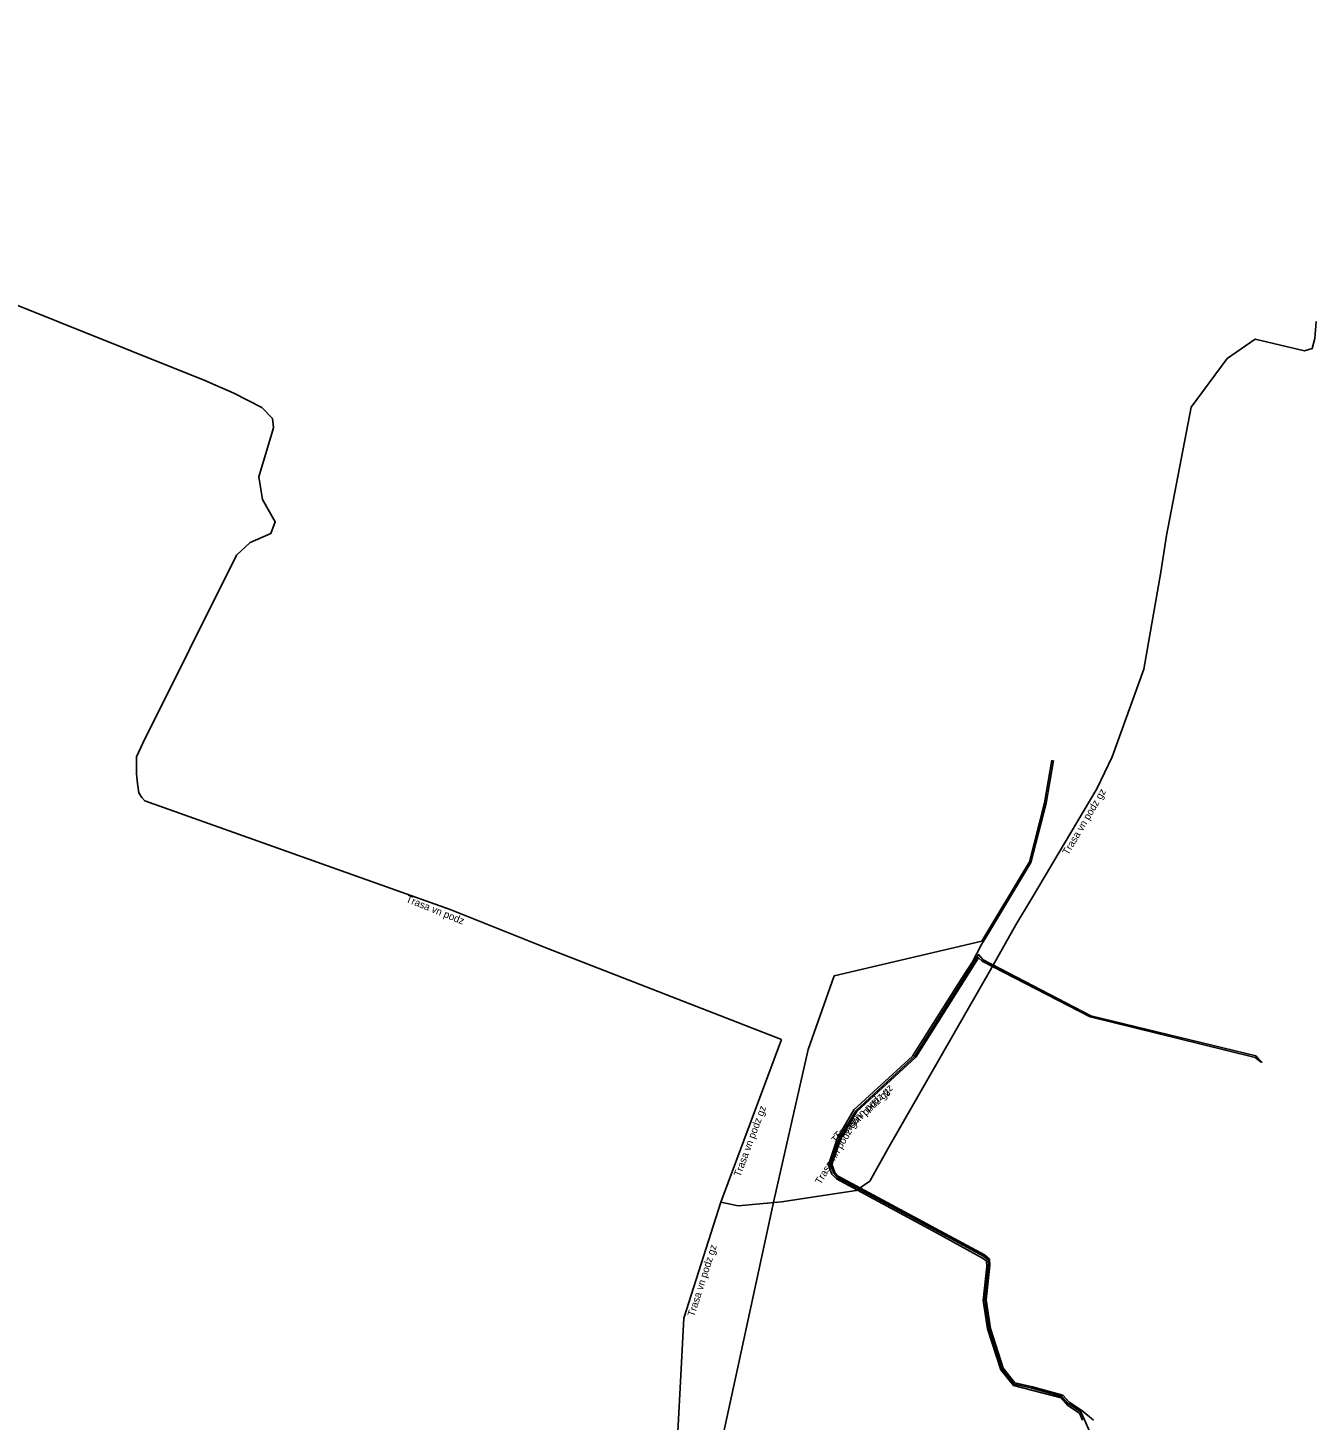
# Model space of a CAD drawing. Extents: x -875087 to -874407, y -1056142 to -1055396.
# Drawn here: x -874544 to -874455.7, y -1055813.9 to -1055718.5 of the extents above; entities that cross this region are included whole.
import ezdxf

# ---------------------------------------------------------------- set-up
doc = ezdxf.new("R2010")
doc.units = 0
for name, color, linetype in [('Popiskový text - Ostatní atributy Trasy', 7, 'Continuous'), ('Spojnice NN', 7, 'Continuous'), ('Spojnice VN', 7, 'Continuous')]:
    doc.layers.add(name, color=color, linetype=linetype)

msp = doc.modelspace()

# ---------------------------------------------------------------- linework, layer by layer
at = {"layer": 'Spojnice NN'}
for points in [[(-874476.442, -1055879.876), (-874476.123, -1055880.406), (-874477.372, -1055886.555), (-874489.374, -1055884.233), (-874490.02, -1055884.117), (-874489.806, -1055882.948), (-874487.818, -1055874.674), (-874485.599, -1055861.083), (-874491.806, -1055849.075), (-874499.666, -1055830.214), (-874495.282, -1055810.035), (-874492.855, -1055798.848), (-874490.498, -1055788.478), (-874488.735, -1055783.434), (-874478.596, -1055781.048), (-874475.337, -1055775.613), (-874474.306, -1055771.567), (-874473.798, -1055768.649)], [(-874473.699, -1055768.666), (-874474.208, -1055771.589), (-874475.244, -1055775.651), (-874478.188, -1055780.57), (-874478.51, -1055781.099), (-874478.618, -1055781.278), (-874479.256, -1055782.458), (-874479.965, -1055783.578), (-874483.348, -1055788.919), (-874487.374, -1055792.616), (-874488.488, -1055794.516), (-874489.116, -1055796.372), (-874488.874, -1055797.014), (-874488.56, -1055797.342), (-874481.664, -1055801.069), (-874478.508, -1055802.796), (-874478.296, -1055802.969), (-874478.267, -1055803.335), (-874478.507, -1055805.664), (-874478.228, -1055807.609), (-874477.304, -1055810.428), (-874476.428, -1055811.497), (-874473.166, -1055812.344), (-874472.713, -1055812.864), (-874471.924, -1055813.383), (-874471.717, -1055813.872)], [(-874459.423, -1055789.295), (-874459.435, -1055789.356), (-874459.828, -1055788.912), (-874471.126, -1055786.16), (-874478.52, -1055782.337), (-874478.838, -1055781.953), (-874479.165, -1055782.516), (-874483.198, -1055788.926), (-874487.248, -1055792.666), (-874488.331, -1055794.487), (-874488.997, -1055796.321), (-874488.757, -1055796.942), (-874488.507, -1055797.243), (-874483.647, -1055799.851), (-874482.116, -1055800.669), (-874478.487, -1055802.633), (-874478.177, -1055802.899), (-874478.15, -1055803.258), (-874478.401, -1055805.632), (-874478.118, -1055807.602), (-874477.23, -1055810.358), (-874476.396, -1055811.4), (-874475.187, -1055811.68), (-874473.127, -1055812.248), (-874472.684, -1055812.719), (-874471.816, -1055813.293), (-874471.57, -1055813.849)], [(-874470.96, -1055813.87), (-874471.76, -1055813.21), (-874472.63, -1055812.63), (-874473.06, -1055812.17), (-874475.14, -1055811.59), (-874476.34, -1055811.31), (-874477.14, -1055810.31), (-874478.02, -1055807.58), (-874478.3, -1055805.63), (-874478.05, -1055803.26), (-874478.08, -1055802.85), (-874478.43, -1055802.55), (-874488.44, -1055797.16), (-874488.67, -1055796.89), (-874488.89, -1055796.32), (-874488.24, -1055794.53), (-874487.17, -1055792.73), (-874483.12, -1055788.99), (-874478.825, -1055782.191), (-874478.586, -1055782.43), (-874471.178, -1055786.226), (-874461.916, -1055788.523), (-874459.867, -1055789.031), (-874459.474, -1055789.336), (-874459.423, -1055789.295)], [(-874471.57, -1055813.849), (-874469.534, -1055818.469), (-874464.404, -1055828.728), (-874462.171, -1055835.73), (-874458.665, -1055845.492), (-874457.632, -1055847.133), (-874456.235, -1055848.653), (-874458.422, -1055863.908), (-874458.653, -1055864.115), (-874463.528, -1055864.698), (-874468.98, -1055864.215), (-874475.059, -1055862.826), (-874480.473, -1055866.45), (-874486.441, -1055870.715), (-874487.718, -1055877.523), (-874488.933, -1055883.904), (-874477.628, -1055886.093), (-874477.456, -1055885.202), (-874476.534, -1055880.44), (-874476.442, -1055879.876)]]:
    msp.add_lwpolyline(points, dxfattribs=at)
at = {"layer": 'Spojnice VN'}
for points in [[(-874592.144, -1055718.468), (-874531.837, -1055742.641), (-874529.864, -1055743.504), (-874527.952, -1055744.491), (-874527.212, -1055745.231), (-874527.15, -1055745.848), (-874527.212, -1055746.094), (-874528.137, -1055749.239), (-874527.89, -1055750.781), (-874527.027, -1055752.322), (-874527.336, -1055753.124), (-874528.753, -1055753.741), (-874529.679, -1055754.604), (-874536.092, -1055767.492), (-874536.524, -1055768.417), (-874536.524, -1055769.589)], [(-874496.48, -1055798.93), (-874495.3, -1055799.18), (-874492.33, -1055798.9), (-874487.22, -1055798.14), (-874486.29, -1055797.5), (-874485.04, -1055795.28), (-874477.83, -1055782.69), (-874476.27, -1055779.93), (-874475.21, -1055778.16), (-874470.73, -1055770.62), (-874469.68, -1055768.41), (-874467.51, -1055762.42), (-874466.35, -1055755.76), (-874465.96, -1055753.25), (-874464.26, -1055744.46), (-874461.8, -1055741.13), (-874459.87, -1055739.8), (-874456.49, -1055740.6), (-874455.96, -1055740.45), (-874455.78, -1055739.75), (-874455.697, -1055738.589)], [(-874536.524, -1055769.589), (-874536.466, -1055770.237), (-874536.378, -1055770.887), (-874536.156, -1055771.213), (-874535.963, -1055771.434), (-874515.04, -1055778.878), (-874508.3, -1055781.575), (-874492.34, -1055787.79)], [(-874496.48, -1055798.93), (-874492.34, -1055787.79)], [(-874499.02, -1055806.89), (-874496.48, -1055798.93)], [(-874499.02, -1055806.89), (-874500.268, -1055830.266), (-874492.837, -1055847.885), (-874483.497, -1055865.879), (-874473.648, -1055877.348), (-874476.357, -1055879.881)]]:
    msp.add_lwpolyline(points, dxfattribs=at)

# ---------------------------------------------------------------- texts
at = {"layer": 'Popiskový text - Ostatní atributy Trasy'}
for s, rotation, p in [('Trasa vn podz gz', 59.28272, (-874472.691, -1055775.193)), ('Trasa vn podz', 338.19383, (-874518.118, -1055778.347)), ('Trasa nn podz gz', 42.72114, (-874488.627, -1055794.96)), ('Trasa nn podz gz', 42.72143, (-874488.46, -1055794.67)), ('Trasa vn podz gz', 69.61323, (-874495.157, -1055797.236)), ('Trasa nn podz gz', 59.60868, (-874489.642, -1055797.767)), ('Trasa vn podz gz', 72.30235, (-874498.314, -1055806.817))]:
    msp.add_text(s, height=0.5, rotation=rotation, dxfattribs=at).set_placement(p)

doc.saveas('drawing.dxf')
